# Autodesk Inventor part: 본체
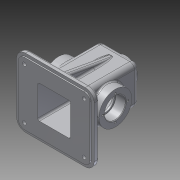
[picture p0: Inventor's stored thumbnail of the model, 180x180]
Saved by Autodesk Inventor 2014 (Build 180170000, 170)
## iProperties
Created: 2016-06
Part Number: 본체
Material: Aluminum 6061
Document SubType Name: Modeling
Designer: user
Density: 2.71 g/cm^3
Appearance: Aluminum - Flat
Mass: 810.193 g
Surface Area: 906.022 cm^2
Volume: 298.964 cm^3
Author: user
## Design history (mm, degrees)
sketch "Sketch1"
  geometry: L1 (65, -57.5)-(-65, -57.5); L2 (-65, -57.5)-(-65, 57.5); L3 (-65, 57.5)-(65, 57.5); L4 (65, 57.5)-(65, -57.5); 3 further points
  constraints: 8 end point, 2 midpoint, 2 parallel, 1 horizontal, 1 horizontal alignment, 1 perpendicular, 1 vertical alignment
  dimensions: "d0" = 130 distance of L1.start L1.end; "d1" = 115 distance of L1.end L2.end
extrude "Extrusion1" new body sketch "Sketch1" distance "d2" = 8; taper "d3" = 0 deg
fillet "Fillet1" dims "d4" = 15
sketch "Sketch2"
  geometry: L1 (-65, 42.5)-(-65, -42.5) reference; L2 (-50, -57.5)-(50, -57.5) reference; L3 (65, -42.5)-(65, 42.5) reference; L4 (50, 57.5)-(-50, 57.5) reference; L5 (-60, 42.5)-(-60, -42.5); L6 (-50, -52.5)-(50, -52.5); L7 (60, -42.5)-(60, 42.5); L8 (50, 52.5)-(-50, 52.5); A1 r 15 centre (-50, 42.5) between (-50, 57.5) and (-65, 42.5) reference; A2 r 15 centre (-50, -42.5) between (-65, -42.5) and (-50, -57.5) reference; A3 r 15 centre (50, -42.5) between (50, -57.5) and (65, -42.5) reference; A4 r 15 centre (50, 42.5) between (65, 42.5) and (50, 57.5) reference; A5 r 10 centre (-50, 42.5) between (-50, 52.5) and (-60, 42.5); A6 r 10 centre (-50, -42.5) between (-60, -42.5) and (-50, -52.5); A7 r 10 centre (50, -42.5) between (50, -52.5) and (60, -42.5); A8 r 10 centre (50, 42.5) between (60, 42.5) and (50, 52.5); 1 further point
  constraints: 8 end point, 8 point on circle, 4 centre point, 7 other
  dimensions: "d5" = 5 distance between parallel lines of L4 L8
extrude "Extrusion2" join sketch "Sketch2" distance "d6" = 2; taper "d7" = 0 deg
sketch "Sketch3"
  geometry: C1 r 7.5 at (-50, 42.5); C2 r 7.5 at (50, 42.5); C3 r 7.5 at (50, -42.5); C4 r 7.5 at (-50, -42.5); A1 r 15 centre (-50, -42.5) between (-65, -42.5) and (-50, -57.5) reference; A2 r 15 centre (50, -42.5) between (50, -57.5) and (65, -42.5) reference; A3 r 15 centre (50, 42.5) between (65, 42.5) and (50, 57.5) reference; A4 r 15 centre (-50, 42.5) between (-50, 57.5) and (-65, 42.5) reference; 1 further point
  constraints: 4 centre point, 4 coincident, 3 equal radius
  dimensions: "d8" = 7.5 radius of C1
extrude "Extrusion3" join sketch "Sketch3" distance "d9" = 3; taper "d10" = 0 deg
fillet "Fillet2" dims "d11" = 3
hole "Hole1" diameter "d14" = 6; stored, may be unused: countersink angle "d18" = 90 deg, drill point angle "d20" = 118 deg; dims "d12" = 10, "d13" = 10, "d15" = 6, "d16" = 4, "d17" = 2, "d19" = 8
pattern_linear "Rectangular Pattern1" dims "d23" = 85
sketch "Sketch4"
  geometry: L1 (-32.5, 32.5)-(32.5, 32.5); L2 (32.5, 32.5)-(32.5, -32.5); L3 (32.5, -32.5)-(-32.5, -32.5); L4 (-32.5, -32.5)-(-32.5, 32.5); 3 further points
  constraints: 8 end point, 2 midpoint, 2 parallel, 1 horizontal, 1 horizontal alignment, 1 perpendicular, 1 vertical alignment
  dimensions: "d27" = 65 distance of L1.start L1.end; "d28" = 65 distance of L1.end L2.end
extrude "Extrusion4" join sketch "Sketch4" distance "d29" = 100; taper "d30" = 0 deg
fillet "Fillet6" dims "d42" = 8
sketch "Sketch6"
  geometry: L1 (75, -10)-(-10, -10) reference; C1 r 27.5 at (32.5, 45); 2 further points
  constraints: 1 centre point, 1 midpoint, 1 vertical alignment
  dimensions: "d37" = 27.5 radius of C1; "d38" = 55 distance from line of C1.centre L1
extrude "Extrusion6" join sketch "Sketch6" distance "d39" = 15; taper "d40" = 0 deg
mirror "Mirror1"
fillet "Fillet5" dims "d41" = 3
fillet "Fillet7" dims "d43" = 8
hole "Hole2" diameter "d46" = 30; stored, may be unused: countersink angle "d50" = 90 deg, drill point angle "d52" = 0 deg; dims "d47" = 6, "d48" = 35, "d49" = 17, "d51" = 20, "d53" = 10, "d54" = 10
mirror "Mirror2"
sketch "Sketch7"
  geometry: L1 (-27.5, 27.5)-(27.5, 27.5); L2 (27.5, 27.5)-(27.5, -27.5); L3 (27.5, -27.5)-(-27.5, -27.5); L4 (-27.5, -27.5)-(-27.5, 27.5); 3 further points
  constraints: 8 end point, 2 midpoint, 2 parallel, 2 perpendicular, 1 horizontal, 1 horizontal alignment, 1 vertical alignment
  dimensions: "d55" = 55 distance of L1.start L1.end
extrude "Extrusion7" cut sketch "Sketch7" distance "d56" = 105; taper "d57" = 0 deg
fillet "Fillet8" dims "d58" = 3
fillet "Fillet9" dims "d59" = 3
workplane "Work Plane1"
sketch "Sketch16"
  geometry: C1 r 20 at (0, 0); 1 further point
  constraints: 1 centre point, 1 coincident
  dimensions: "d130" = 20 radius of C1
fillet "Fillet10" dims "d63" = 1
sketch "Sketch9" dims "d73" = 42
  geometry: C1 r 17.5 at (0, 0) reference; C2 r 27.5 at (0, 0) reference; 3 further points
  constraints: 2 vertical alignment, 1 coincident, 2 other
hole "Hole4" sketch "Sketch9" at (0, 21) diameter "d74" = 3.242; stored, may be unused: countersink angle "d78" = 90 deg, drill point angle "d80" = 118 deg; dims "d75" = 8, "d76" = 35, "d77" = 17, "d79" = 10
pattern_circular "Circular Pattern1" dims angle "d82" = 360 deg
mirror "Mirror3"
sketch "Sketch11"
  geometry: L1 (5, -57.5)-(0, -57.5) reference; L2 (8, -53)-(8, -32) reference; L3 (8, -47.5)-(93.069, -32.5); L4 (100, -32.5)-(8, -32.5) reference; 2 further points
  constraints: 2 end point, 2 point on line
  dimensions: "d95" = 10 distance from line of L1 L3.start; "d96" = 10 deg angle of L3 L1
feature "Rib1" sketch "Sketch11" dims "d97" = 1, "d98" = 10, "d99" = 0, "d100" = 0, "d101" = 1, "d102" = 1
fillet "Fillet11" dims "d103" = 3
extrude "Extrusion9" join sketch "Sketch16" distance "d131" = 10; taper "d132" = 5 deg
fillet "Fillet12" dims "d104" = 3
mirror "Mirror4"
sketch "Sketch13"
  geometry: L1 (-32.5, 47)-(-32.5, -44) reference; L2 (-20, 65)-(20, 65) reference; 3 further points
  constraints: 1 other
  dimensions: "d157" = 26 distance from line of point (0, 39) L2; "d158" = 32.5 distance from line of point (0, 39) L1
emboss "Emboss1" sketch "Sketch13" dims "d107" = 0.5, "d108" = 0
sketch "Sketch14"
  geometry: L1 (42.5, 25.5)-(42.5, 8); L2 (27.5, -2)-(27.5, 100) reference; L3 (47.5, 25.5)-(35.5, 25.5) reference; L4 (60.5, 8)-(39.5, 8) reference; 1 further point
  constraints: 2 end point, 2 point on line, 1 vertical
  dimensions: "d109" = 15 distance between parallel lines of L2 L1
feature "Rib2" sketch "Sketch14" dims "d111" = 1, "d112" = 6, "d113" = 0, "d114" = 0, "d115" = 1, "d116" = 1
fillet "Fillet13" dims "d117" = 3
fillet "Fillet14" dims "d118" = 3
mirror "Mirror5"
chamfer "Chamfer2" distance "d122" = 1; stored, may be unused: second distance "d123" = 2, angle "d124" = 45 deg
chamfer "Chamfer3" distance "d125" = 1; stored, may be unused: second distance "d126" = 2, angle "d127" = 45 deg
fillet "Fillet15" dims "d128" = 0.3
sketch "Sketch17" dims "d133" = 14.5
  geometry: 3 further points
  constraints: 3 vertical alignment, 1 coincident, 2 other
hole "Hole6" sketch "Sketch17" at (0, 14.5) diameter "d134" = 2.459; stored, may be unused: countersink angle "d138" = 90 deg, drill point angle "d140" = 118 deg; dims "d135" = 7, "d136" = 35, "d137" = 17, "d139" = 9
pattern_circular "Circular Pattern3" dims angle "d142" = 360 deg
hole "Hole7" diameter "d146" = 21; stored, may be unused: countersink angle "d150" = 90 deg, drill point angle "d152" = 118 deg; dims "d144" = 10, "d145" = 10, "d147" = 21, "d148" = 35, "d149" = 17, "d151" = 9
chamfer "Chamfer4" distance "d153" = 1; stored, may be unused: second distance "d154" = 2, angle "d155" = 45 deg
fillet "Fillet16" dims "d156" = 3
body "Solid1"
